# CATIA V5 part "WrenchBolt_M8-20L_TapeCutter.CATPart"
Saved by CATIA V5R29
Part number: WrenchBolt_M8-20L_TapeCutter
Bounding box of the stored display mesh (mm): x -6.635 to 6.635, y -6.625 to 6.625, z -20 to 8
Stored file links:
  C:\Users\Administrator\Desktop\프로젝트\Boxfold\TapeCutter\WrenchBolt_M8-20L.CATPart
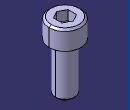
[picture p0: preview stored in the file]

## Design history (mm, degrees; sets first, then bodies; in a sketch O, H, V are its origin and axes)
Body1 (main body)
  Sketch1 on xy-plane, origin (0, 0, 0), H (1, 0, 0), V (0, 1, 0)
    circle A1 centre (0, 0) radius 6.635
    radius A1 = 6.635
  Pad1: profile Sketch1, direction (0, 0, 1), length 8
  Sketch2 on start face of Pad1, origin (0, 0, 0), H (1, 0, 0), V (0, -1, 0)
    circle A1 centre (0, 0) radius 4
    radius A1 = 4
  Pad2: profile Sketch2, direction (0, 0, -1), length 20
  Sketch3 on end face of Pad1, origin (0, 0, 8), H (1, 0, 0), V (0, 1, 0)
    point P1 (3.0475, 0)
    construction circle A1 centre (0, 0) radius 3.5189
    construction circle A2 centre (0, 0) radius 3.0475
    point P2 (3.0475, -1.7595)
    point P3 (3.0475, 1.7595)
    point P4 (0, 3.5189)
    point P5 (-3.0475, 1.7595)
    point P6 (-3.0475, -1.7595)
    point P7 (0, -3.5189)
    line L1 (3.0475, -1.7595) -> (3.0475, 1.7595)
    line L2 (3.0475, 1.7595) -> (0, 3.5189)
    line L3 (0, 3.5189) -> (-3.0475, 1.7595)
    line L4 (-3.0475, 1.7595) -> (-3.0475, -1.7595)
    line L5 (-3.0475, -1.7595) -> (0, -3.5189)
    line L6 (0, -3.5189) -> (3.0475, -1.7595)
    construction line L7 (0, 0) -> (3.0475, 0)
    radius A2 = 3.0475
    coincidence: A1 P2, A1 P3, A1 P4, A1 P5, A1 P6, A1 P7
    tangency: A2 L1, A2 L2, A2 L3, A2 L4, A2 L5, A2 L6
    midpoint: P1 L1
    horizontal: L7 H
  Pocket1: profile Sketch3, direction (0, 0, -1), length 4
  Thread1: "M8", diameter 8, depth 20, pitch 1.25, on face of Pad2 from Sketch2.A1, from end face of Pad2
  Chamfer1: length 0.8, angle 45, on end face of Pad2; edge [face of Pad1 from Sketch1.A1 | end face of Pad1]
  Fillet1: radius 0.4, on edge [start face of Pad1 | face of Pad2 from Sketch2.A1]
